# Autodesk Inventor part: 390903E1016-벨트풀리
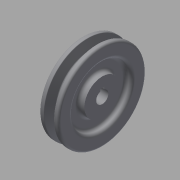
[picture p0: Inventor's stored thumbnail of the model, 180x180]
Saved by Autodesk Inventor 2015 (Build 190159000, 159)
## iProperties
Created: 2019-09
Part Number: 390903E1016-벨트풀리
Material: 일반
Document SubType Name: Modeling
Designer: CAD02
Density: 1 g/cm^3
Appearance: 기본값
Mass: 75.5644 g
Surface Area: 223.132 cm^2
Volume: 75.5644 cm^3
Author: CAD02
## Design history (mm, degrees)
sketch "스케치1"
  geometry: C1 r 42.7 at (0, 0); 1 further point
  constraints: 1 centre point, 1 coincident
  dimensions: "d0" = 85.4 diameter of C1
extrude "돌출1" new body sketch "스케치1" stored distance "d1" = 19; taper "d2" = 0 deg
sketch "스케치2"
  geometry: L1 (9.5, 42.7)-(9.5, -42.7) reference; L2 (9.5, -42.7)-(-9.5, -42.7) reference; L3 (-9.5, -42.7)-(-9.5, 42.7) reference; L4 (-9.5, 42.7)-(9.5, 42.7) reference; L5 (9.5, 42.7)-(-9.5, 42.7) reference; L6 (4.877, 42.7)-(1.953, 33.7); L7 (1.953, 33.7)-(-1.953, 33.7); L8 (-1.953, 33.7)-(-4.877, 42.7); L9 (4, 40)-(-4, 40); L10 (0, 42.7)-(0, 33.7); L11 (13.3, 0)-(-13.3, 0) reference; 1 further point
  constraints: 10 end point, 4 point on line, 2 horizontal, 2 midpoint, 1 vertical, 1 other
  dimensions: "d3" = 6.3 distance between parallel lines of L7 L9; "d4" = 2.7 distance between parallel lines of L4 L9; "d5" = 36 deg angle of L8 L6; "d6" = 8 distance of L9.start L9.end
revolve "회전1" sketch "스케치2" stored, may be unused: angle "d7" = 90 deg
fillet "모깎기1" dims "d8" = 2
fillet "모깎기2" dims "d9" = 0.5
fillet "모깎기3" dims "d10" = 1
sketch "스케치3"
  geometry: C1 r 40.7 at (0, 0) reference; C2 r 17.5 at (0, 0); C3 r 29 at (0, 0)
  constraints: 2 centre point, 2 coincident
  dimensions: "d11" = 58 diameter of C3; "d12" = 35 diameter of C2
extrude "돌출2" cut sketch "스케치3" distance "d13" = 6; taper "d14" = 0 deg
fillet "모깎기4" dims "d15" = 3
fillet "모깎기5" dims "d16" = 3
sketch "스케치4"
  geometry: C1 r 17.5 at (0, 0) reference
extrude "돌출3" join sketch "스케치4" distance "d17" = 5; taper "d18" = 0 deg
sketch "스케치5"
  geometry: C1 r 17.5 at (0, 0) reference
hole "구멍1" sketch "스케치5" at (0, 0) diameter "d19" = 12; stored, may be unused: countersink angle "d23" = 90 deg, drill point angle "d25" = 118 deg; dims "d20" = 6, "d21" = 4, "d22" = 2, "d24" = 8
sketch "스케치6"
  geometry: L1 (7.8, 2)-(0, 2); L2 (0, 2)-(0, -2); L3 (0, -2)-(7.8, -2); L4 (7.8, -2)-(7.8, 2); C1 r 6 at (0, 0) reference; 1 further point
  constraints: 8 end point, 2 parallel, 1 coincident, 1 horizontal, 1 midpoint, 1 perpendicular
  dimensions: "d26" = 4 distance of L3.end L1.start; "d27" = 13.8 dimension on C1 L4
extrude "돌출4" cut sketch "스케치6" stored distance "d28" = 5; taper "d29" = 0 deg
node "솔리드1"
mirror "대칭1"
node "절단 모서리 투영1"
